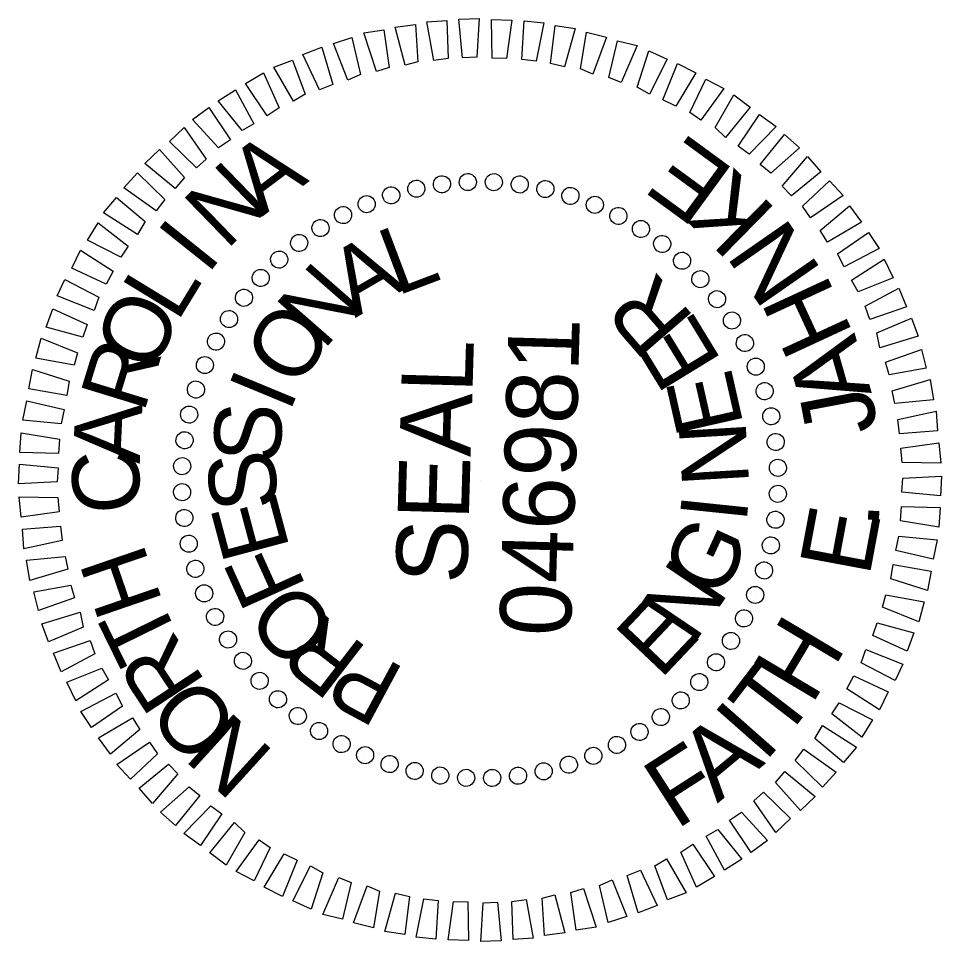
# Model space of a CAD drawing. Extents: x 2097002 to 2098146, y 685127 to 687089.
# Drawn here: x 2097176 to 2097253.7, y 687011.1 to 687088.8 of the extents above; entities that cross this region are included whole.
import ezdxf

# ---------------------------------------------------------------- set-up
doc = ezdxf.new("R2010")
doc.units = 0
doc.layers.add('Sheet PE Seal Cell', color=7, linetype='Continuous')

msp = doc.modelspace()

# ---------------------------------------------------------------- linework, layer by layer
at = {"layer": 'Sheet PE Seal Cell'}
for p, q in [((2097209.44, 687074.455), (2097209.44, 687074.455)), ((2097211.65, 687074.791), (2097211.65, 687074.791)), ((2097213.808, 687075.029), (2097213.808, 687075.029)), ((2097216.009, 687075.015), (2097216.009, 687075.015)), ((2097218.204, 687074.801), (2097218.204, 687074.801)), ((2097207.323, 687073.917), (2097207.323, 687073.917)), ((2097220.342, 687074.388), (2097220.342, 687074.388)), ((2097222.428, 687073.878), (2097222.428, 687073.878)), ((2097205.301, 687073.175), (2097205.301, 687073.175)), ((2097224.507, 687073.117), (2097224.507, 687073.117)), ((2097203.323, 687072.232), (2097203.323, 687072.232)), ((2097226.48, 687072.159), (2097226.48, 687072.159)), ((2097201.39, 687071.138), (2097201.39, 687071.138)), ((2097228.4, 687071.103), (2097228.4, 687071.103)), ((2097199.604, 687069.939), (2097199.604, 687069.939)), ((2097230.163, 687069.801), (2097230.163, 687069.801)), ((2097197.912, 687068.488), (2097197.912, 687068.488)), ((2097231.873, 687068.401), (2097231.873, 687068.401)), ((2097196.367, 687066.982), (2097196.367, 687066.982)), ((2097233.379, 687066.856), (2097233.379, 687066.856)), ((2097194.967, 687065.272), (2097194.967, 687065.272)), ((2097234.831, 687065.163), (2097234.831, 687065.163)), ((2097193.665, 687063.509), (2097193.665, 687063.509)), ((2097236.029, 687063.378), (2097236.029, 687063.378)), ((2097192.609, 687061.589), (2097192.609, 687061.589)), ((2097237.123, 687061.445), (2097237.123, 687061.445)), ((2097191.651, 687059.616), (2097191.651, 687059.616)), ((2097238.066, 687059.467), (2097238.066, 687059.467)), ((2097190.89, 687057.537), (2097190.89, 687057.537)), ((2097238.808, 687057.445), (2097238.808, 687057.445)), ((2097190.38, 687055.451), (2097190.38, 687055.451)), ((2097239.347, 687055.328), (2097239.347, 687055.328)), ((2097189.967, 687053.312), (2097189.967, 687053.312)), ((2097239.683, 687053.117), (2097239.683, 687053.117)), ((2097189.753, 687051.117), (2097189.753, 687051.117)), ((2097239.92, 687050.96), (2097239.92, 687050.96)), ((2097214.83, 687049.938), (2097214.83, 687049.938)), ((2097189.739, 687048.917), (2097189.739, 687048.917)), ((2097239.906, 687048.759), (2097239.906, 687048.759)), ((2097189.977, 687046.759), (2097189.977, 687046.759)), ((2097239.692, 687046.564), (2097239.692, 687046.564)), ((2097190.313, 687044.548), (2097190.313, 687044.548)), ((2097239.28, 687044.425), (2097239.28, 687044.425)), ((2097190.851, 687042.432), (2097190.851, 687042.432)), ((2097238.769, 687042.339), (2097238.769, 687042.339)), ((2097191.593, 687040.409), (2097191.593, 687040.409)), ((2097238.008, 687040.261), (2097238.008, 687040.261)), ((2097192.536, 687038.431), (2097192.536, 687038.431)), ((2097237.05, 687038.288), (2097237.05, 687038.288)), ((2097193.63, 687036.499), (2097193.63, 687036.499)), ((2097235.994, 687036.368), (2097235.994, 687036.368)), ((2097194.829, 687034.713), (2097194.829, 687034.713)), ((2097234.692, 687034.605), (2097234.692, 687034.605)), ((2097196.28, 687033.02), (2097196.28, 687033.02)), ((2097233.292, 687032.895), (2097233.292, 687032.895)), ((2097197.786, 687031.476), (2097197.786, 687031.476)), ((2097231.748, 687031.389), (2097231.748, 687031.389)), ((2097199.496, 687030.075), (2097199.496, 687030.075)), ((2097230.055, 687029.937), (2097230.055, 687029.937)), ((2097201.259, 687028.774), (2097201.259, 687028.774)), ((2097228.269, 687028.739), (2097228.269, 687028.739)), ((2097203.179, 687027.717), (2097203.179, 687027.717)), ((2097226.337, 687027.644), (2097226.337, 687027.644)), ((2097205.152, 687026.76), (2097205.152, 687026.76)), ((2097224.358, 687026.702), (2097224.358, 687026.702)), ((2097207.231, 687025.999), (2097207.231, 687025.999)), ((2097222.336, 687025.96), (2097222.336, 687025.96)), ((2097209.317, 687025.488), (2097209.317, 687025.488)), ((2097211.456, 687025.076), (2097211.456, 687025.076)), ((2097213.65, 687024.862), (2097213.65, 687024.862)), ((2097215.851, 687024.848), (2097215.851, 687024.848)), ((2097218.009, 687025.085), (2097218.009, 687025.085)), ((2097220.219, 687025.421), (2097220.219, 687025.421))]:
    msp.add_line(p, q, dxfattribs=at)
for points in [[(2097210.953, 687085.216), (2097210.348, 687088.485), (2097212.051, 687088.585), (2097212.158, 687085.381)], [(2097213.361, 687085.446), (2097213.055, 687088.706), (2097214.758, 687088.757), (2097214.563, 687085.511)], [(2097215.861, 687085.423), (2097215.806, 687088.676), (2097217.505, 687088.627), (2097217.061, 687085.388)], [(2097218.359, 687085.301), (2097218.553, 687088.546), (2097220.2, 687088.398), (2097219.555, 687085.166)], [(2097206.125, 687084.306), (2097205.068, 687087.538), (2097206.726, 687087.79), (2097207.184, 687084.625)], [(2097208.541, 687084.836), (2097207.683, 687088.012), (2097209.391, 687088.262), (2097209.599, 687085.105)], [(2097220.75, 687084.981), (2097221.143, 687088.171), (2097222.837, 687087.922), (2097221.943, 687084.696)], [(2097203.702, 687083.576), (2097202.492, 687086.662), (2097204.057, 687087.167), (2097204.766, 687084.045)], [(2097223.288, 687084.507), (2097223.778, 687087.594), (2097225.467, 687087.195), (2097224.326, 687084.077)], [(2097201.327, 687082.744), (2097199.914, 687085.737), (2097201.532, 687086.34), (2097202.441, 687083.212)], [(2097225.668, 687083.788), (2097226.408, 687086.867), (2097228.047, 687086.47), (2097226.706, 687083.357)], [(2097228.045, 687082.968), (2097229.035, 687086.041), (2097230.565, 687085.346), (2097229.079, 687082.388)], [(2097199.149, 687081.807), (2097197.481, 687084.657), (2097199.049, 687085.262), (2097200.116, 687082.38)], [(2097230.215, 687081.905), (2097231.455, 687084.97), (2097232.982, 687084.175), (2097231.3, 687081.373)], [(2097196.912, 687080.572), (2097195.09, 687083.276), (2097196.617, 687084.182), (2097197.932, 687081.242)], [(2097232.485, 687080.838), (2097233.817, 687083.651), (2097235.345, 687082.856), (2097233.417, 687080.211)], [(2097194.825, 687079.332), (2097192.797, 687081.842), (2097194.274, 687082.749), (2097195.792, 687079.904)], [(2097234.599, 687079.576), (2097236.18, 687082.332), (2097237.55, 687081.291), (2097235.476, 687078.75)], [(2097192.833, 687077.889), (2097190.65, 687080.254), (2097192.03, 687081.264), (2097193.852, 687078.56)], [(2097236.555, 687078.019), (2097238.333, 687080.668), (2097239.754, 687079.677), (2097237.486, 687077.341)], [(2097190.982, 687076.192), (2097188.696, 687078.41), (2097189.93, 687079.574), (2097191.804, 687076.919)], [(2097238.41, 687076.464), (2097240.435, 687079.006), (2097241.703, 687077.869), (2097239.29, 687075.738)], [(2097189.181, 687074.444), (2097186.642, 687076.569), (2097187.876, 687077.733), (2097189.958, 687075.372)], [(2097240.259, 687074.66), (2097242.382, 687077.149), (2097243.495, 687075.866), (2097241.035, 687073.837)], [(2097187.576, 687072.59), (2097184.881, 687074.519), (2097186.019, 687075.786), (2097188.304, 687073.519)], [(2097241.96, 687072.96), (2097244.223, 687075.095), (2097245.388, 687073.86), (2097242.632, 687071.99)], [(2097186.017, 687070.584), (2097183.169, 687072.418), (2097184.257, 687073.687), (2097186.649, 687071.666)], [(2097243.451, 687070.915), (2097245.913, 687072.995), (2097246.923, 687071.615), (2097244.073, 687069.947)], [(2097184.611, 687068.674), (2097181.802, 687070.107), (2097182.695, 687071.581), (2097185.239, 687069.606)], [(2097244.895, 687068.973), (2097247.498, 687070.748), (2097248.41, 687069.421), (2097245.463, 687067.856)], [(2097183.395, 687066.409), (2097180.483, 687067.744), (2097181.227, 687069.273), (2097183.977, 687067.492)], [(2097246.081, 687066.737), (2097248.834, 687068.508), (2097249.588, 687066.935), (2097246.653, 687065.77)], [(2097182.38, 687064.187), (2097179.265, 687065.428), (2097179.905, 687066.81), (2097182.763, 687065.327)], [(2097247.218, 687064.553), (2097250.063, 687066.071), (2097250.718, 687064.502), (2097247.636, 687063.441)], [(2097181.415, 687061.964), (2097178.338, 687062.804), (2097178.883, 687064.339), (2097181.795, 687063.004)], [(2097248.204, 687062.324), (2097251.14, 687063.539), (2097251.696, 687062.022), (2097248.467, 687061.065)], [(2097180.696, 687059.584), (2097177.461, 687060.178), (2097177.911, 687061.866), (2097180.976, 687060.627)], [(2097248.932, 687059.851), (2097251.964, 687060.914), (2097252.369, 687059.351), (2097249.251, 687058.792)], [(2097180.072, 687057.051), (2097176.886, 687057.594), (2097177.184, 687059.236), (2097180.256, 687058.246)], [(2097249.512, 687057.434), (2097252.691, 687058.392), (2097252.992, 687056.682), (2097249.731, 687056.377)], [(2097179.602, 687054.664), (2097176.359, 687054.958), (2097176.707, 687056.599), (2097179.837, 687055.858)], [(2097249.992, 687055.019), (2097253.214, 687055.725), (2097253.316, 687054.072), (2097250.107, 687053.815)], [(2097179.38, 687052.169), (2097176.131, 687052.264), (2097176.229, 687053.912), (2097179.464, 687053.367)], [(2097250.222, 687052.611), (2097253.437, 687053.068), (2097253.587, 687051.363), (2097250.337, 687051.407)], [(2097179.26, 687049.772), (2097176.004, 687049.616), (2097176.102, 687051.264), (2097179.345, 687050.97)], [(2097250.399, 687050.105), (2097253.655, 687050.26), (2097253.557, 687048.612), (2097250.315, 687048.907)], [(2097179.437, 687047.266), (2097176.222, 687046.809), (2097176.072, 687048.514), (2097179.322, 687048.469)], [(2097250.28, 687047.707), (2097253.528, 687047.613), (2097253.43, 687045.965), (2097250.195, 687046.509)], [(2097179.667, 687044.858), (2097176.445, 687044.151), (2097176.343, 687045.805), (2097179.552, 687046.062)], [(2097250.057, 687045.213), (2097253.3, 687044.918), (2097252.952, 687043.278), (2097249.822, 687044.019)], [(2097180.147, 687042.443), (2097176.968, 687041.485), (2097176.668, 687043.194), (2097179.928, 687043.5)], [(2097249.588, 687042.825), (2097252.773, 687042.282), (2097252.475, 687040.64), (2097249.403, 687041.63)], [(2097180.727, 687040.025), (2097177.695, 687038.963), (2097177.29, 687040.525), (2097180.408, 687041.085)], [(2097248.964, 687040.292), (2097252.198, 687039.698), (2097251.749, 687038.01), (2097248.683, 687039.25)], [(2097181.456, 687037.553), (2097178.519, 687036.338), (2097177.963, 687037.854), (2097181.192, 687038.811)], [(2097248.244, 687037.912), (2097251.321, 687037.072), (2097250.776, 687035.538), (2097247.864, 687036.873)], [(2097182.441, 687035.323), (2097179.596, 687033.805), (2097178.941, 687035.375), (2097182.023, 687036.436)], [(2097247.279, 687035.689), (2097250.395, 687034.448), (2097249.754, 687033.066), (2097246.896, 687034.55)], [(2097183.578, 687033.139), (2097180.826, 687031.369), (2097180.071, 687032.941), (2097183.006, 687034.106)], [(2097246.264, 687033.468), (2097249.177, 687032.133), (2097248.432, 687030.604), (2097245.683, 687032.384)], [(2097184.764, 687030.904), (2097182.161, 687029.129), (2097181.249, 687030.456), (2097184.196, 687032.021)], [(2097245.048, 687031.202), (2097247.858, 687029.77), (2097246.964, 687028.295), (2097244.421, 687030.27)], [(2097186.208, 687028.961), (2097183.747, 687026.882), (2097182.736, 687028.262), (2097185.586, 687029.93)], [(2097243.642, 687029.292), (2097246.49, 687027.459), (2097245.402, 687026.19), (2097243.01, 687028.21)], [(2097187.699, 687026.917), (2097185.436, 687024.782), (2097184.272, 687026.016), (2097187.027, 687027.887)], [(2097242.083, 687027.287), (2097244.778, 687025.358), (2097243.641, 687024.09), (2097241.356, 687026.357)], [(2097189.401, 687025.217), (2097187.277, 687022.727), (2097186.164, 687024.01), (2097188.624, 687026.04)], [(2097240.478, 687025.433), (2097243.018, 687023.308), (2097241.783, 687022.143), (2097239.701, 687024.505)], [(2097191.249, 687023.412), (2097189.224, 687020.87), (2097187.957, 687022.007), (2097190.37, 687024.138)], [(2097238.677, 687023.684), (2097240.963, 687021.467), (2097239.729, 687020.302), (2097237.855, 687022.958)], [(2097193.104, 687021.858), (2097191.327, 687019.208), (2097189.905, 687020.2), (2097192.174, 687022.535)], [(2097236.827, 687021.987), (2097239.009, 687019.623), (2097237.629, 687018.613), (2097235.807, 687021.317)], [(2097195.06, 687020.3), (2097193.479, 687017.545), (2097192.109, 687018.585), (2097194.184, 687021.126)], [(2097234.834, 687020.545), (2097236.862, 687018.035), (2097235.385, 687017.127), (2097233.867, 687019.972)], [(2097197.174, 687019.038), (2097195.842, 687016.226), (2097194.314, 687017.02), (2097196.242, 687019.666)], [(2097232.747, 687019.305), (2097234.569, 687016.601), (2097233.042, 687015.695), (2097231.727, 687018.634)], [(2097199.444, 687017.972), (2097198.205, 687014.907), (2097196.677, 687015.701), (2097198.359, 687018.504)], [(2097230.51, 687018.069), (2097232.178, 687015.219), (2097230.61, 687014.615), (2097229.543, 687017.497)], [(2097201.614, 687016.908), (2097200.625, 687013.836), (2097199.094, 687014.531), (2097200.581, 687017.489)], [(2097228.332, 687017.132), (2097229.746, 687014.14), (2097228.127, 687013.536), (2097227.218, 687016.664)], [(2097203.991, 687016.089), (2097203.252, 687013.009), (2097201.613, 687013.407), (2097202.954, 687016.519)], [(2097225.957, 687016.301), (2097227.168, 687013.214), (2097225.602, 687012.709), (2097224.893, 687015.831)], [(2097206.372, 687015.369), (2097205.882, 687012.282), (2097204.193, 687012.682), (2097205.334, 687015.8)], [(2097223.535, 687015.571), (2097224.591, 687012.339), (2097222.933, 687012.087), (2097222.475, 687015.251)], [(2097208.909, 687014.896), (2097208.516, 687011.706), (2097206.823, 687011.955), (2097207.717, 687015.18)], [(2097211.301, 687014.576), (2097211.106, 687011.33), (2097209.46, 687011.478), (2097210.104, 687014.711)], [(2097218.706, 687014.661), (2097219.311, 687011.392), (2097217.608, 687011.291), (2097217.501, 687014.496)], [(2097221.118, 687015.041), (2097221.976, 687011.865), (2097220.268, 687011.614), (2097220.06, 687014.771)], [(2097213.798, 687014.453), (2097213.854, 687011.2), (2097212.154, 687011.25), (2097212.599, 687014.488)], [(2097216.298, 687014.431), (2097216.604, 687011.17), (2097214.902, 687011.12), (2097215.096, 687014.365)]]:
    msp.add_lwpolyline(points, close=True, dxfattribs=at)
for centre, major_axis in [((2097211.628, 687074.813), (-0.092, 0.714)), ((2097213.808, 687074.997), (-0.029, 0.719)), ((2097215.996, 687074.991), (0.033, 0.719)), ((2097218.175, 687074.794), (0.096, 0.714)), ((2097207.357, 687073.879), (-0.215, 0.687)), ((2097209.472, 687074.439), (-0.154, 0.703)), ((2097220.329, 687074.408), (0.158, 0.702)), ((2097222.44, 687073.836), (0.218, 0.686)), ((2097205.299, 687073.137), (-0.274, 0.666)), ((2097224.494, 687073.081), (0.277, 0.664)), ((2097203.313, 687072.218), (-0.331, 0.64)), ((2097226.474, 687072.151), (0.334, 0.638)), ((2097201.415, 687071.129), (-0.385, 0.608)), ((2097228.366, 687071.052), (0.389, 0.606)), ((2097199.619, 687069.879), (-0.437, 0.572)), ((2097230.155, 687069.791), (0.44, 0.57)), ((2097197.939, 687068.478), (-0.485, 0.532)), ((2097231.827, 687068.38), (0.488, 0.529)), ((2097196.388, 687066.935), (-0.529, 0.488)), ((2097233.369, 687066.829), (0.532, 0.485)), ((2097194.976, 687065.263), (-0.57, 0.44)), ((2097234.771, 687065.149), (0.572, 0.437)), ((2097193.716, 687063.475), (-0.606, 0.389)), ((2097236.021, 687063.353), (0.608, 0.385)), ((2097192.617, 687061.583), (-0.638, 0.334)), ((2097237.109, 687061.455), (0.64, 0.331)), ((2097191.687, 687059.603), (-0.664, 0.277)), ((2097238.028, 687059.469), (0.666, 0.274)), ((2097190.932, 687057.549), (-0.686, 0.218)), ((2097238.771, 687057.411), (0.687, 0.215)), ((2097190.36, 687055.437), (-0.702, 0.158)), ((2097239.331, 687055.296), (0.703, 0.154)), ((2097189.974, 687053.284), (-0.714, 0.096)), ((2097239.704, 687053.14), (0.714, 0.092)), ((2097189.777, 687051.104), (-0.719, 0.033)), ((2097239.889, 687050.96), (0.719, 0.029)), ((2097189.77, 687048.917), (-0.719, -0.029)), ((2097239.883, 687048.772), (0.719, -0.033)), ((2097189.955, 687046.736), (-0.714, -0.092)), ((2097239.686, 687046.593), (0.714, -0.096)), ((2097190.329, 687044.581), (-0.703, -0.154)), ((2097239.299, 687044.439), (0.702, -0.158)), ((2097190.889, 687042.466), (-0.687, -0.215)), ((2097238.727, 687042.328), (0.686, -0.218)), ((2097191.631, 687040.407), (-0.666, -0.274)), ((2097237.973, 687040.274), (0.664, -0.277)), ((2097192.55, 687038.422), (-0.64, -0.331)), ((2097237.042, 687038.294), (0.638, -0.334)), ((2097193.639, 687036.524), (-0.608, -0.385)), ((2097235.943, 687036.402), (0.606, -0.389)), ((2097194.888, 687034.728), (-0.572, -0.437)), ((2097234.683, 687034.613), (0.57, -0.44)), ((2097196.29, 687033.048), (-0.532, -0.485)), ((2097233.272, 687032.941), (0.529, -0.488)), ((2097197.833, 687031.496), (-0.488, -0.529)), ((2097231.72, 687031.399), (0.485, -0.532)), ((2097199.505, 687030.085), (-0.44, -0.57)), ((2097230.04, 687029.997), (0.437, -0.572)), ((2097201.293, 687028.825), (-0.389, -0.606)), ((2097228.244, 687028.747), (0.385, -0.608)), ((2097203.185, 687027.725), (-0.334, -0.638)), ((2097226.346, 687027.659), (0.331, -0.64)), ((2097205.165, 687026.795), (-0.277, -0.664)), ((2097224.361, 687026.74), (0.274, -0.666)), ((2097207.219, 687026.041), (-0.218, -0.686)), ((2097222.302, 687025.997), (0.215, -0.687)), ((2097209.331, 687025.468), (-0.158, -0.702)), ((2097211.484, 687025.082), (-0.096, -0.714)), ((2097213.663, 687024.885), (-0.033, -0.719)), ((2097215.851, 687024.879), (0.029, -0.719)), ((2097218.032, 687025.063), (0.092, -0.714)), ((2097220.187, 687025.437), (0.154, -0.703))]:
    msp.add_ellipse(centre, major_axis=major_axis, ratio=0.999708, dxfattribs=at)

# ---------------------------------------------------------------- texts
for s, height, rotation, p in [('A', 5.639, 36.95198, (2097196.515, 687072.08)), ('E', 5.998, 143.82785, (2097236.386, 687075.925)), ('N', 5.639, 44.15374, (2097193.481, 687069.217)), ('K', 5.998, 135.54393, (2097239.905, 687072.548)), ('I', 5.638, 51.35497, (2097191.869, 687067.113)), ('N', 5.998, 124.8181, (2097243.675, 687067.486)), ('L', 5.639, 20.73568, (2097207.826, 687065.398)), ('A', 5.639, 30.0951, (2097204.321, 687063.549)), ('N', 5.639, 48.81144, (2097201.639, 687060.776)), ('L', 5.638, 58.5557, (2097189.352, 687063.134)), ('R', 5.639, 130.81624, (2097232.982, 687063.517)), ('H', 5.998, 114.83412, (2097246.28, 687062.22)), ('O', 5.638, 65.75599, (2097187.375, 687058.79)), ('O', 5.638, 58.16831, (2097199.543, 687057.486)), ('E', 5.638, 121.45892, (2097235.228, 687059.9)), ('046981', 5.9982, 88.33483, (2097222.458, 687036.74)), ('A', 5.998, 105.99381, (2097247.794, 687057.24)), ('R', 5.638, 72.95593, (2097186.528, 687055.463)), ('SEAL', 5.9982, 88.33483, (2097213.726, 687041.168)), ('I', 5.638, 67.52443, (2097198.785, 687055.507)), ('E', 5.638, 102.74659, (2097237.023, 687054.545)), ('J', 5.998, 100.73599, (2097248.325, 687054.189)), ('A', 5.638, 87.35515, (2097186.206, 687051.271)), ('S', 5.638, 86.23523, (2097197.96, 687051.229)), ('N', 5.638, 93.39122, (2097237.479, 687049.58)), ('C', 5.638, 94.5547, (2097186.391, 687047.314)), ('S', 5.638, 95.59044, (2097197.905, 687047.629)), ('E', 5.638, 104.9459, (2097198.855, 687044.15)), ('I', 5.638, 84.03603, (2097237.232, 687046.236)), ('E', 5.998, 79.39252, (2097247.574, 687041.706)), ('.', 5.998, 86.50186, (2097248.341, 687045.822)), ('G', 5.638, 65.32507, (2097235.142, 687039.744)), ('H', 5.638, 108.95431, (2097188.17, 687039.659)), ('F', 5.638, 114.30186, (2097200.261, 687040.908)), ('N', 5.638, 55.96879, (2097232.783, 687036.011)), ('O', 5.639, 133.01607, (2097203.114, 687037.523)), ('E', 5.638, 46.61172, (2097229.996, 687033.09)), ('T', 5.638, 116.1546, (2097189.725, 687036.362)), ('R', 5.639, 142.37448, (2097205.512, 687035.703)), ('H', 5.998, 59.20818, (2097242.723, 687030.914)), ('R', 5.639, 123.35534, (2097191.825, 687032.9)), ('T', 5.998, 52.40794, (2097240.274, 687027.745)), ('P', 5.639, 151.73372, (2097208.664, 687034.011)), ('O', 5.639, 130.55657, (2097194.823, 687029.361)), ('I', 5.998, 48.60599, (2097238.747, 687026.106)), ('N', 5.639, 137.75833, (2097197.655, 687026.978)), ('A', 5.998, 39.76568, (2097234.8, 687022.714)), ('F', 5.998, 32.74907, (2097231.325, 687020.478))]:
    msp.add_text(s, height=height, rotation=rotation, dxfattribs=at).set_placement(p)

doc.saveas('drawing.dxf')
